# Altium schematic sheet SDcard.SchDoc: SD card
size A4; Author: Daniela Catanzaro; CompanyName: Arduino srl; DocumentNumber: ASX00055; SheetNumber: 6; SheetTotal: 10; RevAuthor: Daniela Catanzaro
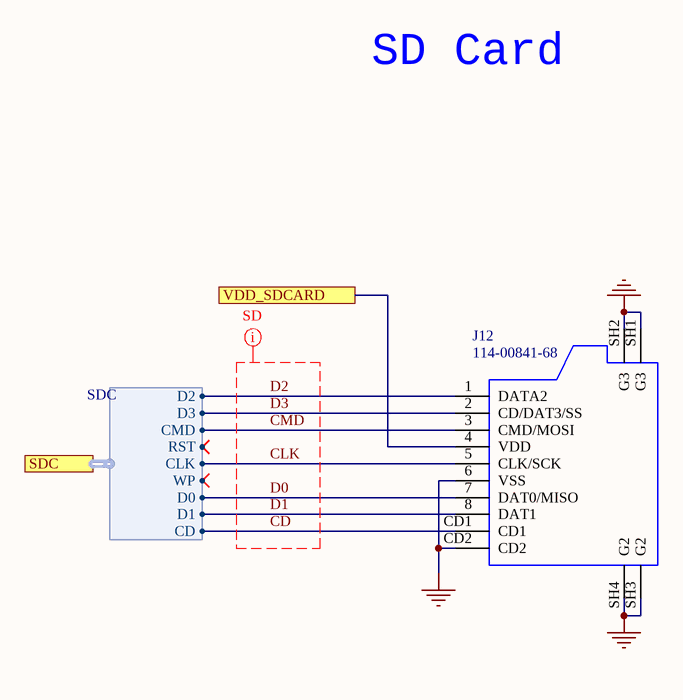
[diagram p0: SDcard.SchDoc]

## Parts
J12  114-00841-68  [AMPHENOL_114-00841-68]

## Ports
SDC (harness SDC), VDD_SDCARD

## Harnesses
SDC: D0, D1, D2, D3, CMD, CLK, CD, WP, RST

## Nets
GND: J12.6(VSS) J12.CD2 J12.SH1(G3) J12.SH2(G3) J12.SH3(G2) J12.SH4(G2)
CD: J12.CD1 ; port SDC.CD
CLK: J12.5(CLK/SCK) ; port SDC.CLK
CMD: J12.3(CMD/MOSI) ; port SDC.CMD
D0: J12.7(DAT0/MISO) ; port SDC.D0
D1: J12.8(DAT1) ; port SDC.D1
D2: J12.1(DATA2) ; port SDC.D2
D3: J12.2(CD/DAT3/SS) ; port SDC.D3
VDD_SDCARD: J12.4(VDD) ; port VDD_SDCARD

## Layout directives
net class SD; net class DIFFERENTIAL: CD, CLK, CMD, D0, D1, D2, D3

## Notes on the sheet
- SD Card

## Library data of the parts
J12 = J0011-A.5: CONN Micro SD; Manufacturer: Amphenol; Code Arduino: A5328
